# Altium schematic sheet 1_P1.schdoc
size 307 x 218 mm; Symbol: Drawing-Symbol_A4; Device: Drawing-Symbol_A4; @Project Name: grandPA2; @Page Count: 1; @Update Date: 2026-07-21; @Create Date: 2026-07-16; @Schematic Name: main; @Page No: 1; @Page Name: P1; Company: EasyEDA.com; Version: v0.2; Page Size: A4; @Create Time: 16:22:10; @Update Time: 17:14:25; Width: 1170; Height: 825; Region Start: 1; X Region Count: 6; Y Region Count: 4; Blade Width: 10; Title Block Position: 3; @Board Name: main
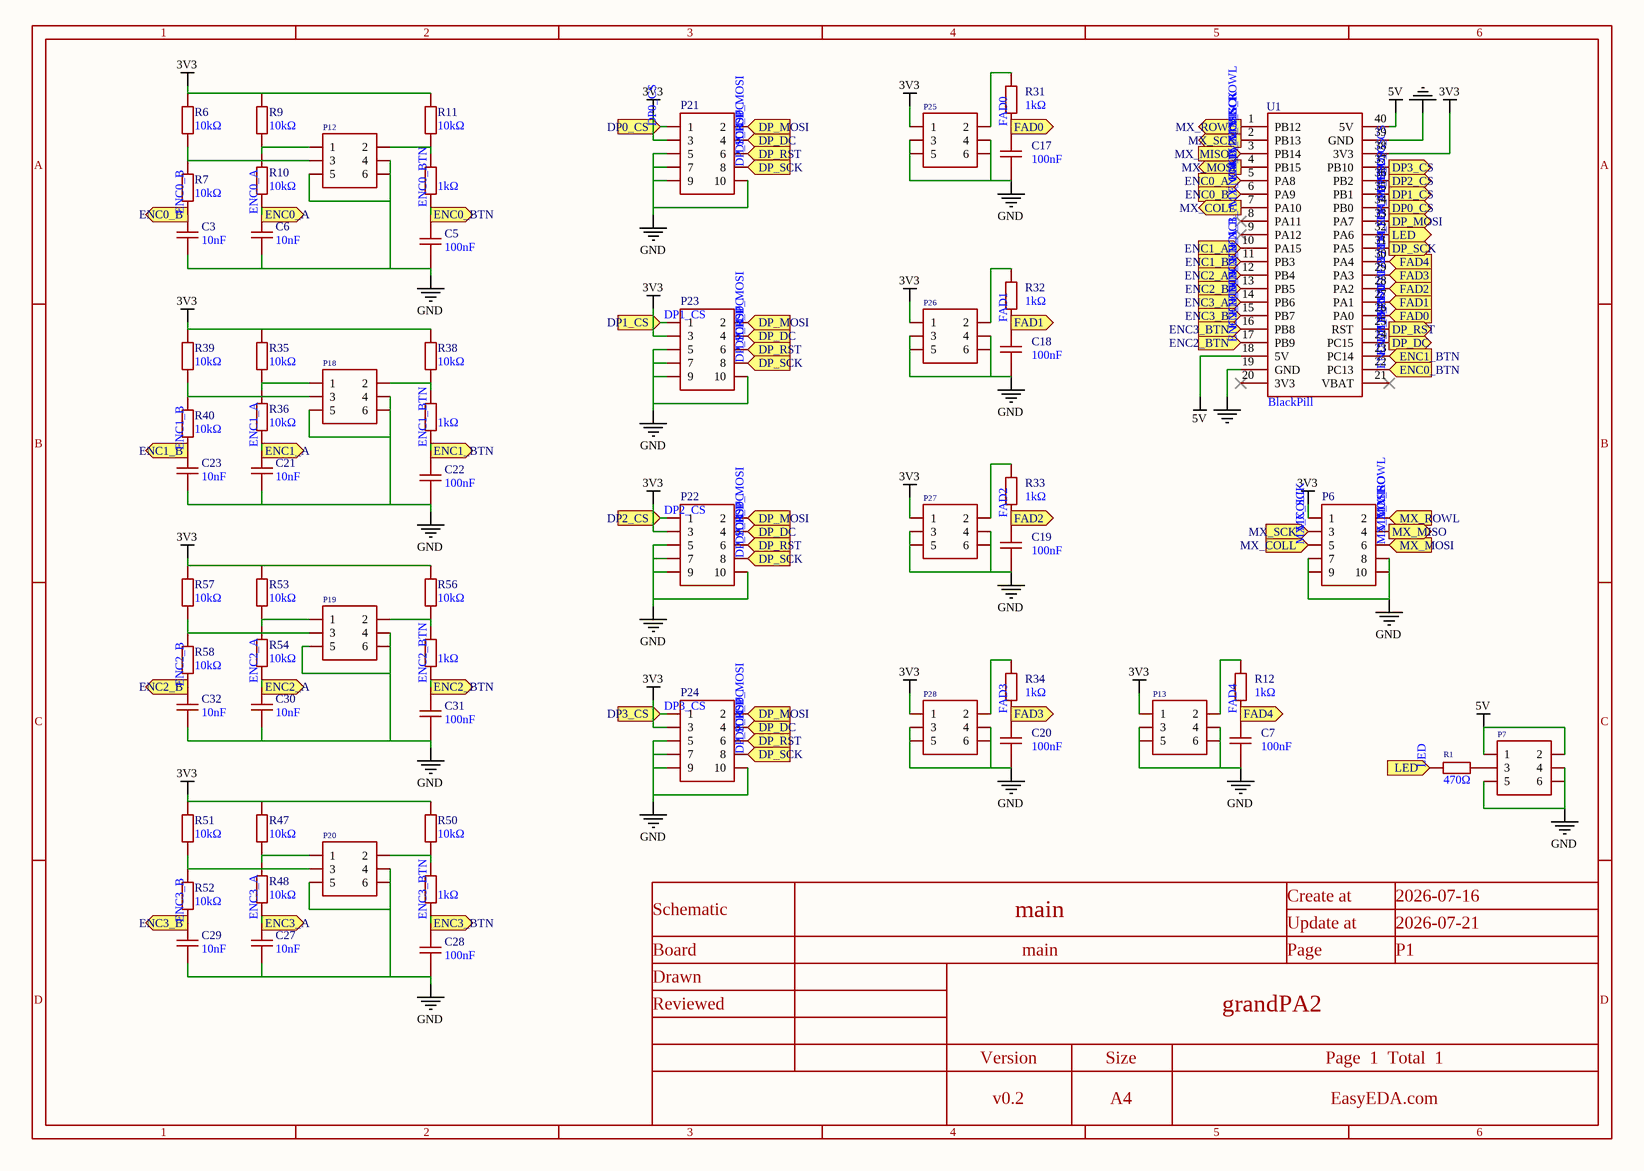
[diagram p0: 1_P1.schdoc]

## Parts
C3  10nF  [C0402]
C5  100nF  [C0402]
C6  10nF  [C0402]
C7  100nF  [C0402]
C17  100nF  [C0402]
C18  100nF  [C0402]
C19  100nF  [C0402]
C20  100nF  [C0402]
C21  10nF  [C0402]
C22  100nF  [C0402]
C23  10nF  [C0402]
C27  10nF  [C0402]
C28  100nF  [C0402]
C29  10nF  [C0402]
C30  10nF  [C0402]
C31  100nF  [C0402]
C32  10nF  [C0402]
P6  2.54-2*5P简牛  [IDC-TH_10P-P2.54_C5665]  (value not drawn)
P7  2.54-2*3P简牛  [IDC-TH_6P-P2.54_C11214]  (value not drawn)
P12  2.54-2*3P简牛  [IDC-TH_6P-P2.54_C11214]  (value not drawn)
P13  2.54-2*3P简牛  [IDC-TH_6P-P2.54_C11214]  (value not drawn)
P18  2.54-2*3P简牛  [IDC-TH_6P-P2.54_C11214]  (value not drawn)
P19  2.54-2*3P简牛  [IDC-TH_6P-P2.54_C11214]  (value not drawn)
P20  2.54-2*3P简牛  [IDC-TH_6P-P2.54_C11214]  (value not drawn)
P21  2.54-2*5P简牛  [IDC-TH_10P-P2.54_C5665]  (value not drawn)
P22  2.54-2*5P简牛  [IDC-TH_10P-P2.54_C5665]  (value not drawn)
P23  2.54-2*5P简牛  [IDC-TH_10P-P2.54_C5665]  (value not drawn)
P24  2.54-2*5P简牛  [IDC-TH_10P-P2.54_C5665]  (value not drawn)
P25  2.54-2*3P简牛  [IDC-TH_6P-P2.54_C11214]  (value not drawn)
P26  2.54-2*3P简牛  [IDC-TH_6P-P2.54_C11214]  (value not drawn)
P27  2.54-2*3P简牛  [IDC-TH_6P-P2.54_C11214]  (value not drawn)
P28  2.54-2*3P简牛  [IDC-TH_6P-P2.54_C11214]  (value not drawn)
R1  470Ω  [R0402]
R5  1kΩ  [R0402]
R6  10kΩ  [R0402]
R7  10kΩ  [R0402]
R9  10kΩ  [R0402]
R10  10kΩ  [R0402]
R11  10kΩ  [R0402]
R12  1kΩ  [R0402]
R31  1kΩ  [R0402]
R32  1kΩ  [R0402]
R33  1kΩ  [R0402]
R34  1kΩ  [R0402]
R35  10kΩ  [R0402]
R36  10kΩ  [R0402]
R37  1kΩ  [R0402]
R38  10kΩ  [R0402]
R39  10kΩ  [R0402]
R40  10kΩ  [R0402]
R47  10kΩ  [R0402]
R48  10kΩ  [R0402]
R49  1kΩ  [R0402]
R50  10kΩ  [R0402]
R51  10kΩ  [R0402]
R52  10kΩ  [R0402]
R53  10kΩ  [R0402]
R54  10kΩ  [R0402]
R55  1kΩ  [R0402]
R56  10kΩ  [R0402]
R57  10kΩ  [R0402]
R58  10kΩ  [R0402]
U1  BlackPill  [Z_module_black_pill_STM32F411]

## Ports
DP0_CS (in), DP0_CS (out), DP1_CS (in), DP1_CS (out), DP2_CS (in), DP2_CS (out), DP3_CS (in), DP3_CS (out), DP_DC (in), DP_DC (out), DP_MOSI (in), DP_MOSI (out), DP_RST (in), DP_RST (out), DP_SCK (in), DP_SCK (out), ENC0_A (in), ENC0_A (out), ENC0_B (in), ENC0_B (out), ENC0_BTN (in), ENC0_BTN (out), ENC1_A (in), ENC1_A (out), ENC1_B (in), ENC1_B (out), ENC1_BTN (in), ENC1_BTN (out), ENC2_A (in), ENC2_A (out), ENC2_B (in), ENC2_B (out), ENC2_BTN (in), ENC2_BTN (out), ENC3_A (in), ENC3_A (out), ENC3_B (in), ENC3_B (out), ENC3_BTN (in), ENC3_BTN (out), FAD0 (in), FAD0 (out), FAD1 (in), FAD1 (out), FAD2 (in), FAD2 (out), FAD3 (in), FAD3 (out), FAD4 (in), FAD4 (out), LED (in), LED (out), MX_COLL (in), MX_COLL (out), MX_MISO (in), MX_MISO (out), MX_MOSI (in), MX_MOSI (out), MX_ROWL (in), MX_ROWL (out), MX_SCK (in), MX_SCK (out)

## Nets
3V3: P6.1 P13.1 P21.3 P22.3 P23.3 P24.3 P25.1 P26.1 P27.1 P28.1 R6.2 R9.2 R11.2 R35.2 R38.2 R39.2 R47.2 R50.2 R51.2 R53.2 R56.2 R57.2 U1.38(3V3)
5V: P7.1 P7.2 U1.18(5V) U1.40(5V)
GND: C3.1 C5.2 C6.1 C7.2 C17.2 C18.2 C19.2 C20.2 C21.1 C22.2 C23.1 C27.1 C28.2 C29.1 C30.1 C31.2 C32.1 P6.7 P6.8 P6.9 P6.10 P7.4 P7.5 P7.6 P12.4 P12.5 P12.6 P13.3 P13.4 P13.5 P13.6 P18.4 P18.5 P18.6 P19.4 P19.5 P19.6 P20.4 P20.5 P20.6 P21.5 P21.7 P21.9 P21.10 P22.5 P22.7 P22.9 P22.10 P23.5 P23.7 P23.9 P23.10 P24.5 P24.7 P24.9 P24.10 P25.3 P25.4 P25.5 P25.6 P26.3 P26.4 P26.5 P26.6 P27.3 P27.4 P27.5 P27.6 P28.3 P28.4 P28.5 P28.6 U1.19(GND) U1.39(GND)
DP0_CS: P21.1 U1.34(PB0) ; port DP0_CS
DP1_CS: P23.1 U1.35(PB1) ; port DP1_CS
DP2_CS: P22.1 U1.36(PB2) ; port DP2_CS
DP3_CS: P24.1 U1.37(PB10) ; port DP3_CS
DP_DC: P21.4 P22.4 P23.4 P24.4 U1.24(PC15) ; port DP_DC
DP_MOSI: P21.2 P22.2 P23.2 P24.2 U1.33(PA7) ; port DP_MOSI
DP_RST: P21.6 P22.6 P23.6 P24.6 U1.25(RST) ; port DP_RST
DP_SCK: P21.8 P22.8 P23.8 P24.8 U1.31(PA5) ; port DP_SCK
ENC0_A: C6.2 R10.1 U1.5(PA8) ; port ENC0_A
ENC0_B: C3.2 R7.1 U1.6(PA9) ; port ENC0_B
ENC0_BTN: C5.1 R5.1 U1.22(PC13) ; port ENC0_BTN
ENC1_A: C21.2 R36.1 U1.10(PA15) ; port ENC1_A
ENC1_B: C23.2 R40.1 U1.11(PB3) ; port ENC1_B
ENC1_BTN: C22.1 R37.1 U1.23(PC14) ; port ENC1_BTN
ENC2_A: C30.2 R54.1 U1.12(PB4) ; port ENC2_A
ENC2_B: C32.2 R58.1 U1.13(PB5) ; port ENC2_B
ENC2_BTN: C31.1 R55.1 U1.17(PB9) ; port ENC2_BTN
ENC3_A: C27.2 R48.1 U1.14(PB6) ; port ENC3_A
ENC3_B: C29.2 R52.1 U1.15(PB7) ; port ENC3_B
ENC3_BTN: C28.1 R49.1 U1.16(PB8) ; port ENC3_BTN
FAD0: C17.1 R31.1 U1.26(PA0) ; port FAD0
FAD1: C18.1 R32.1 U1.27(PA1) ; port FAD1
FAD2: C19.1 R33.1 U1.28(PA2) ; port FAD2
FAD3: C20.1 R34.1 U1.29(PA3) ; port FAD3
FAD4: C7.1 R12.1 U1.30(PA4) ; port FAD4
LED: R1.1 U1.32(PA6) ; port LED
MX_COLL: P6.5 U1.7(PA10) ; port MX_COLL
MX_MISO: P6.4 U1.3(PB14) ; port MX_MISO
MX_MOSI: P6.6 U1.4(PB15) ; port MX_MOSI
MX_ROWL: P6.2 U1.1(PB12) ; port MX_ROWL
MX_SCK: P6.3 U1.2(PB13) ; port MX_SCK
NetP7_3: P7.3 R1.2
NetP12_1: P12.1 R9.1 R10.2
NetP12_2: P12.2 R5.2 R11.1
NetP12_3: P12.3 R6.1 R7.2
NetP13_2: P13.2 R12.2
NetP18_1: P18.1 R35.1 R36.2
NetP18_2: P18.2 R37.2 R38.1
NetP18_3: P18.3 R39.1 R40.2
NetP19_1: P19.1 R53.1 R54.2
NetP19_2: P19.2 R55.2 R56.1
NetP19_3: P19.3 R57.1 R58.2
NetP20_1: P20.1 R47.1 R48.2
NetP20_2: P20.2 R49.2 R50.1
NetP20_3: P20.3 R51.1 R52.2
NetP25_2: P25.2 R31.2
NetP26_2: P26.2 R32.2
NetP27_2: P27.2 R33.2
NetP28_2: P28.2 R34.2

Not connected (* = marked no-connect by the designer): U1 8(PA11)* 9(PA12)* 20(3V3)* 21(VBAT)*

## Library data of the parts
C3 C6 C21 C23 C27 C29 C30 C32 = CL05B103KB5NNNC: Manufacturer: SAMSUNG(三星); Add into BOM: yes; Tolerance: ±10%; Voltage Rating: 50V; Temperature Coefficient: X7R
C5 C7 C17-C20 C22 C28 C31 = CL05B104KO5NNNC: Manufacturer: SAMSUNG(三星); Add into BOM: yes; Tolerance: ±10%; Voltage Rating: 16V; Temperature Coefficient: X7R
P6 P21-P24 = 2.54-2*5P简牛: Manufacturer: BOOMELE(博穆精密); Symbol: HDR-IDC-2.54-2X5P; Add into BOM: yes; Connector Type: IDC Header; Pitch: 2.54mm; Number of Positions or Pins: 2x5P; Current Rating: 1A; Holder Type: Through Hole; Number of PINs Per Row: 5
P7 P12 P13 P18-P20 P25-P28 = 2.54-2*3P简牛: Manufacturer: BOOMELE(博穆精密); Symbol: HDR-IDC-2.54-2X3P; Add into BOM: yes; Connector Type: IDC Header; Pitch: 2.54mm; Number of Positions or Pins: 2x3P; Current Rating: 1A; Holder Type: Through Hole; Number of PINs Per Row: 3
R1 = 0402WGF4700TCE: Manufacturer: UNI-ROYAL(厚声); Add into BOM: yes; Tolerance: ±1%; Power(Watts): 62.5mW; Voltage-Supply(Max): 50V; Temperature Coefficient: ±100ppm/℃
R5 R12 R31-R34 R37 R49 R55 = 0402WGF1001TCE: Manufacturer: UNI-ROYAL(厚声); Add into BOM: yes; Tolerance: ±1%; Power(Watts): 62.5mW; Voltage-Supply(Max): 50V; Temperature Coefficient: ±100ppm/℃
R6 R7 R9-R11 R35 R36 R38-R40 R47 R48 R50-R54 R56-R58 = 0402WGF1002TCE: Manufacturer: UNI-ROYAL(厚声); Add into BOM: yes; Tolerance: ±1%; Power(Watts): 62.5mW; Voltage-Supply(Max): 50V; Temperature Coefficient: ±100ppm/℃
U1 = YAAJ_BlackPill: Add into BOM: yes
